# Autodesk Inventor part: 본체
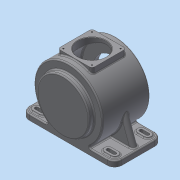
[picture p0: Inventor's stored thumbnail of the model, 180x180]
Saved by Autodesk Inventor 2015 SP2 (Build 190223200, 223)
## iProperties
Created: 2015-06
Part Number: 본체
Material: 일반
Document SubType Name: Modeling
Designer: AMC
Density: 1 g/cm^3
Appearance: 기본값
Author: AMC
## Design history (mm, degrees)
sketch "스케치1"
  geometry: L1 (-115, 59)-(115, 59); L2 (115, 59)-(115, -59); L3 (115, -59)-(-115, -59); L4 (-115, -59)-(-115, 59); 3 further points
  constraints: 8 end point, 2 midpoint, 2 parallel, 1 horizontal, 1 horizontal alignment, 1 perpendicular, 1 vertical alignment
  dimensions: "d0" = 230 distance of L1.start L1.end; "d1" = 118 distance of L1.end L2.end
extrude "돌출1" new body sketch "스케치1" distance "d2" = 14; taper "d3" = 0 deg
sketch "스케치2"
  geometry: L1 (-97, -59)-(97, -59) reference; L2 (97, 59)-(-97, 59) reference; L3 (97, 50)-(81, 50); L4 (81, 32)-(97, 32); A1 r 9 centre (97, 41) between (97, 32) and (97, 50); A2 r 9 centre (81, 41) between (81, 50) and (81, 32); 1 further point
  constraints: 5 point on circle, 4 end point, 4 tangent, 2 centre point, 2 horizontal, 1 point on line
  dimensions: "d11" = 9 radius of A2; "d12" = 16 distance of A1.centre A2.centre; "d13" = 97 horizontal distance of point (0, 0) A1.centre; "d14" = 41 vertical distance of point (0, 0) A2.centre
extrude "돌출2" join sketch "스케치2" distance "d15" = 3; taper "d16" = 0 deg
sketch "스케치3"
  geometry: L1 (81, 32)-(97, 32) reference; L2 (97, 50)-(81, 50) reference; L3 (81, 45)-(97, 45); L4 (81, 37)-(97, 37); A1 r 9 centre (81, 41) between (81, 50) and (81, 32) reference; A2 r 9 centre (97, 41) between (97, 32) and (97, 50) reference; A3 r 4 centre (81, 41) between (81, 45) and (81, 37); A4 r 4 centre (97, 41) between (97, 37) and (97, 45); 1 further point
  constraints: 4 end point, 4 point on circle, 3 tangent, 2 centre point, 2 coincident, 1 equal radius
  dimensions: "d17" = 8 distance between parallel lines of L4 L3
extrude "돌출3" cut sketch "스케치3" stored distance "d18" = 3; taper "d19" = 0 deg
sketch "스케치4"
  geometry: L1 (115, 14)-(115, 0) reference; L2 (115, 0)-(-115, 0) reference; L3 (-115, 0)-(-115, 14) reference; L4 (-115, 14)-(115, 14) reference; C1 r 85 at (0, 85); 1 further point
  constraints: 1 centre point
  dimensions: "d21" = 170 diameter of C1; "d22" = 170 dimension on C1 L2
extrude "돌출4" join sketch "스케치4" stored distance "d23" = 118; taper "d24" = 0 deg
fillet "모깎기5" dims "d26" = 18
fillet "모깎기6" dims "d27" = 3
fillet "모깎기7" dims "d28" = 3
fillet "모깎기8" dims "d29" = 3
node "작업 평면1"
sketch "스케치5"
  geometry: L1 (-42.5, -42.5)-(42.5, -42.5); L2 (42.5, -42.5)-(42.5, 42.5); L3 (42.5, 42.5)-(-42.5, 42.5); L4 (-42.5, 42.5)-(-42.5, -42.5); 3 further points
  constraints: 8 end point, 2 midpoint, 2 parallel, 2 perpendicular, 1 horizontal, 1 horizontal alignment, 1 vertical alignment
  dimensions: "d31" = 85 distance of L3.end L1.start
extrude "돌출5" join sketch "스케치5" stored distance "d32" = 118; taper "d33" = 0 deg
fillet "모깎기9" dims "d34" = 7
fillet "모깎기10" dims "d35" = 3
sketch "스케치6"
  geometry: L1 (35.5, -35.5)-(-35.5, -35.5); L2 (-35.5, -35.5)-(-35.5, 35.5); L3 (-35.5, 35.5)-(35.5, 35.5); L4 (35.5, 35.5)-(35.5, -35.5); L5 (35.5, -35.5)-(-35.5, 35.5); L6 (-35.5, -35.5)-(35.5, 35.5); 5 further points
  constraints: 12 end point, 4 coincident, 2 midpoint, 2 parallel, 1 horizontal, 1 perpendicular
  dimensions: "d36" = 71 distance of L1.end L2.end; "d37" = 71 distance of L2.end L3.end
hole "구멍1" sketch "스케치6" at (-35.5, -35.5), (-35.5, 35.5), (35.5, 35.5), (35.5, -35.5) diameter "d38" = 3.242; stored, may be unused: countersink angle "d42" = 90 deg, drill point angle "d44" = 118 deg; dims "d39" = 10, "d40" = 4, "d41" = 2, "d43" = 13
sketch "스케치7"
  geometry: L1 (55.857, 14)-(112, 14) reference; L2 (115, 11)-(115, 0) reference; L3 (115, 0)-(-115, 0) reference; L4 (-115, 0)-(-115, 11) reference; L5 (-112, 14)-(-55.857, 14) reference; L6 (-42.5, 160.324)-(-42.5, 173) reference; L7 (-42.5, 173)-(42.5, 173) reference; L8 (42.5, 173)-(42.5, 160.324) reference; C1 r 77 at (0, 85); A1 r 3 centre (112, 11) between (115, 11) and (112, 14) reference; A2 r 3 centre (-112, 11) between (-112, 14) and (-115, 11) reference; A3 r 3 centre (-55.857, 17) between (-55.857, 14) and (-53.953, 19.318) reference; A4 r 85 centre (0, 85) between (-43.949, 157.756) and (-53.953, 19.318) reference; A5 r 3 centre (-45.5, 160.324) between (-43.949, 157.756) and (-42.5, 160.324) reference; A6 r 3 centre (45.5, 160.324) between (42.5, 160.324) and (43.949, 157.756) reference; A7 r 85 centre (0, 85) between (53.953, 19.318) and (43.949, 157.756) reference; A8 r 3 centre (55.857, 17) between (53.953, 19.318) and (55.857, 14) reference; 1 further point
  constraints: 1 centre point, 1 coincident
  dimensions: "d45" = 154 diameter of C1
extrude "돌출6" cut sketch "스케치7" stored distance "d46" = 102; taper "d47" = 0 deg
sketch "스케치8"
  geometry: L1 (41.143, -11)-(0, -11) reference; L2 (0, 0)-(0, -11) reference; L3 (0, 0)-(194, 0) reference; L4 (194, 0)-(194, -11) reference; L5 (194, -11)-(152.857, -11) reference; C1 r 65 at (97, -85); A1 r 6 centre (152.857, -17) between (152.857, -11) and (149.049, -21.636) reference; A2 r 82 centre (97, -85) between (44.951, -21.636) and (149.049, -21.636) reference; A3 r 6 centre (41.143, -17) between (44.951, -21.636) and (41.143, -11) reference; 1 further point
  constraints: 1 centre point, 1 coincident
  dimensions: "d48" = 130 diameter of C1
extrude "돌출7" join sketch "스케치8" distance "d49" = 3; taper "d50" = 0 deg
fillet "모깎기11" dims "d51" = 3
sketch "스케치9"
  geometry: C1 r 65 at (0, 0) reference; C2 r 47.5 at (0, 0); 1 further point
  constraints: 1 centre point, 1 coincident
  dimensions: "d52" = 95 diameter of C2
extrude "돌출8" cut sketch "스케치9" stored distance "d53" = 3; taper "d54" = 0 deg
sketch "스케치10"
  geometry: C1 r 47.5 at (0, 0) reference; C2 r 65 at (0, 0) reference; 2 further points
  constraints: 1 horizontal alignment
  dimensions: "d55" = 55 distance of C1.centre point (55, 0)
hole "구멍2" sketch "스케치10" at (55, 0) diameter "d56" = 3.242; stored, may be unused: countersink angle "d60" = 90 deg, drill point angle "d62" = 118 deg; dims "d57" = 10, "d58" = 4, "d59" = 2, "d61" = 13
sketch "스케치11"
  geometry: L1 (152.857, 11)-(194, 11) reference; L2 (194, 0)-(194, 11) reference; L3 (194, 0)-(0, 0) reference; L4 (0, 0)-(0, 11) reference; L5 (0, 11)-(41.143, 11) reference; C1 r 65 at (97, 85); A1 r 6 centre (41.143, 17) between (41.143, 11) and (44.951, 21.636) reference; A2 r 82 centre (97, 85) between (149.049, 21.636) and (44.951, 21.636) reference; A3 r 6 centre (152.857, 17) between (149.049, 21.636) and (152.857, 11) reference; 1 further point
  constraints: 1 centre point, 1 coincident
  dimensions: "d66" = 130 diameter of C1
extrude "돌출9" join sketch "스케치11" distance "d67" = 13; taper "d68" = 0 deg
fillet "모깎기12" dims "d69" = 3
sketch "스케치12"
  geometry: L1 (-81, 70.236)-(-97, 70.236) reference; L2 (-103.633, 71)-(-108.18, 71) reference; L3 (-111.967, 74)-(-111.967, 85) reference; L4 (-111.967, 85)-(111.967, 85) reference; L5 (111.967, 85)-(111.967, 74) reference; L6 (108.18, 71)-(103.633, 71) reference; L7 (97, 70.236)-(81, 70.236) reference; L8 (74.367, 71)-(55.857, 71) reference; L9 (-55.857, 71)-(-74.367, 71) reference; C1 r 77 at (0, 0) reference; C2 r 31 at (0, 0); A1 r 3 centre (55.857, 68) between (55.857, 71) and (53.953, 65.682) reference; A2 r 85 centre (0, 0) between (-53.953, 65.682) and (53.953, 65.682) reference; A3 r 3 centre (-55.857, 68) between (-53.953, 65.682) and (-55.857, 71) reference; 1 further point
  constraints: 1 centre point, 1 coincident, 6 other
  dimensions: "d70" = 62 diameter of C2
extrude "돌출10" join sketch "스케치12" distance "d71" = 3.5; taper "d72" = -25 deg
fillet "모깎기13" dims "d73" = 3
hole "구멍3" diameter "d76" = 30; stored, may be unused: countersink angle "d80" = 90 deg, drill point angle "d82" = 0 deg; dims "d74" = 10, "d75" = 10, "d77" = 10, "d78" = 47, "d79" = 14, "d81" = 17
fillet "모깎기14" dims "d83" = 3
fillet "모깎기15" dims "d84" = 0.3
chamfer "모따기1" distance "d85" = 1; stored, may be unused: second distance "d86" = 2, angle "d87" = 45 deg
sketch "스케치13"
  geometry: C1 r 35 at (0, 0); 1 further point
  constraints: 1 centre point, 1 coincident
  dimensions: "d88" = 70 diameter of C1
extrude "돌출11" cut sketch "스케치13" stored distance "d89" = 3.5; taper "d90" = 0 deg
chamfer "모따기2" distance "d91" = 1; stored, may be unused: second distance "d92" = 2, angle "d93" = 45 deg
sketch "스케치14"
  geometry: L1 (55.857, 14)-(112, 14) reference; L2 (115, 11)-(115, 0) reference; L3 (115, 0)-(-115, 0) reference; L4 (-115, 0)-(-115, 11) reference; L5 (-112, 14)-(-55.857, 14) reference; L6 (-42.5, 160.324)-(-42.5, 173) reference; L7 (-42.5, 173)-(-36, 173) reference; L8 (-36, 173)-(-35, 172) reference; L9 (-35, 172)-(-35, 153.586) reference; L10 (35, 153.586)-(35, 172) reference; L11 (35, 172)-(36, 173) reference; L12 (36, 173)-(42.5, 173) reference; L13 (42.5, 173)-(42.5, 160.324) reference; L14 (109, 14)-(97, 14) reference; L15 (109, 14)-(84.87, 80.297); A1 r 3 centre (112, 11) between (115, 11) and (112, 14) reference; A2 r 3 centre (-112, 11) between (-112, 14) and (-115, 11) reference; A3 r 3 centre (-55.857, 17) between (-55.857, 14) and (-53.953, 19.318) reference; A4 r 85 centre (0, 85) between (-43.949, 157.756) and (-53.953, 19.318) reference; A5 r 3 centre (-45.5, 160.324) between (-43.949, 157.756) and (-42.5, 160.324) reference; A6 r 77 centre (0, 85) between (-35, 153.586) and (35, 153.586) reference; A7 r 3 centre (45.5, 160.324) between (42.5, 160.324) and (43.949, 157.756) reference; A8 r 85 centre (0, 85) between (53.953, 19.318) and (43.949, 157.756) reference; A9 r 3 centre (55.857, 17) between (53.953, 19.318) and (55.857, 14) reference; 1 further point
  constraints: 2 end point, 1 point on circle, 1 point on line
  dimensions: "d94" = 6 distance from line of L2 L15.start; "d95" = 110 deg angle of L3 L15
extrude "돌출12" join sketch "스케치14" stored distance "d96" = 15; taper "d97" = 0 deg
fillet "모깎기16" dims "d98" = 7.5
fillet "모깎기17" dims "d99" = 3
fillet "모깎기18" dims "d100" = 7.5
fillet "모깎기19" dims "d101" = 3
node "작업 평면5"
  node "작업 평면4"
sketch "스케치16"
  geometry: L1 (56, 0)-(-56, 0) reference; 3 further points
  constraints: 1 coincident, 1 midpoint, 1 vertical alignment, 1 other
feature "엠보싱1" sketch "스케치16" dims "d106" = 0.5, "d107" = 0
fillet "모깎기20" dims "d108" = 3
fillet "모깎기21" dims "d109" = 3
node "솔리드1"
mirror "대칭1"
mirror "대칭2"
pattern_circular "원형 패턴1" dims angle "d64" = 360 deg
mirror "대칭3"
node "절단 모서리 투영1"
node "절단 모서리 투영2"
node "절단 모서리 투영3"
node "절단 모서리 투영4"
node "절단 모서리 투영5"
node "절단 모서리 투영6"
node "절단 모서리 투영7"
node "절단 모서리 투영8"
node "절단 모서리 투영9"
other parameters: "d30" = -173, "d105" = 25 deg
